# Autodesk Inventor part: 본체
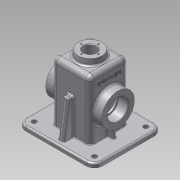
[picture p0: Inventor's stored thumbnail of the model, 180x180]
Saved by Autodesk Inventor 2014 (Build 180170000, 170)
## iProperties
Created: 2016-08
Part Number: 본체
Material: 알루미늄 6061
Document SubType Name: Modeling
Designer: user
Density: 2.71 g/cm^3
Appearance: 알루미늄 - 평지
Mass: 800.3 g
Surface Area: 911.822 cm^2
Volume: 295.314 cm^3
Author: user
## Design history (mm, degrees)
sketch "스케치1"
  geometry: L1 (-60, 52.5)-(60, 52.5); L2 (60, 52.5)-(60, -52.5); L3 (60, -52.5)-(-60, -52.5); L4 (-60, -52.5)-(-60, 52.5); 3 further points
  constraints: 8 end point, 2 midpoint, 2 parallel, 1 horizontal, 1 horizontal alignment, 1 perpendicular, 1 vertical alignment
  dimensions: "d0" = 120 distance of L1.start L1.end; "d1" = 105 distance of L1.end L2.end
extrude "돌출1" new body sketch "스케치1" distance "d2" = 3; taper "d3" = 0 deg
sketch "스케치2"
  geometry: L1 (-65, 57.5)-(65, 57.5); L2 (65, 57.5)-(65, -57.5); L3 (65, -57.5)-(-65, -57.5); L4 (-65, -57.5)-(-65, 57.5); 3 further points
  constraints: 8 end point, 2 midpoint, 2 parallel, 1 horizontal, 1 horizontal alignment, 1 perpendicular, 1 vertical alignment
  dimensions: "d4" = 115 distance of L1.end L2.end; "d5" = 130 distance of L1.start L1.end
extrude "돌출2" join sketch "스케치2" distance "d6" = 7; taper "d7" = 0 deg
fillet "모깎기1" dims "d8" = 14
fillet "모깎기2" dims "d9" = 3
sketch "스케치3"
  geometry: L1 (32.5, 110)-(-32.5, 110); L2 (-32.5, 110)-(-32.5, 0); L3 (-32.5, 0)-(32.5, 0); L4 (32.5, 0)-(32.5, 110); 2 further points
  constraints: 8 end point, 2 parallel, 1 coincident, 1 horizontal, 1 midpoint, 1 perpendicular
  dimensions: "d10" = 65 distance of L1.start L1.end; "d11" = 110 distance of L1.end L2.end
extrude "돌출3" join sketch "스케치3" stored distance "d12" = 65; taper "d13" = 0 deg
fillet "모깎기3" dims "d14" = 8
fillet "모깎기4" dims "d15" = 8
sketch "스케치4"
  geometry: L1 (27.5, 105)-(-27.5, 105); L2 (-27.5, 105)-(-27.5, 0); L3 (-27.5, 0)-(27.5, 0); L4 (27.5, 0)-(27.5, 105); 2 further points
  constraints: 8 end point, 2 parallel, 1 coincident, 1 horizontal, 1 midpoint, 1 perpendicular
  dimensions: "d18" = 105 distance of L1.end L2.end; "d19" = 55 distance of L1.start L1.end
extrude "돌출4" cut sketch "스케치4" stored distance "d20" = 55; taper "d21" = 0 deg
fillet "모깎기6" dims "d22" = 3
fillet "모깎기7" dims "d23" = 3
node "작업 평면1"
sketch "스케치5"
  geometry: C1 r 20 at (0, 0); 1 further point
  constraints: 1 centre point, 1 coincident
  dimensions: "d25" = 40 diameter of C1
extrude "돌출5" join sketch "스케치5" stored distance "d26" = 55; taper "d27" = 7 deg
fillet "모깎기8" dims "d28" = 3
hole "구멍1" diameter "d31" = 21; stored, may be unused: countersink angle "d35" = 90 deg, drill point angle "d37" = 0 deg; dims "d29" = 10, "d30" = 10, "d32" = 6, "d33" = 4, "d34" = 2, "d36" = 8
chamfer "모따기1" distance "d38" = 1; stored, may be unused: second distance "d39" = 2, angle "d40" = 45 deg
node "작업 평면2"
sketch "스케치6"
  geometry: C1 r 27.5 at (0, 55); 1 further point
  constraints: 1 centre point, 1 vertical alignment
  dimensions: "d42" = 55 diameter of C1; "d43" = 55 distance of point (0, 0) C1.centre
extrude "돌출6" join sketch "스케치6" stored distance "d44" = 95; taper "d45" = 0 deg
fillet "모깎기9" dims "d46" = 3
hole "구멍2" diameter "d49" = 30; stored, may be unused: countersink angle "d53" = 90 deg, drill point angle "d55" = 0 deg; dims "d47" = 10, "d48" = 10, "d50" = 6, "d51" = 35, "d52" = 17, "d54" = 8
hole "구멍3" diameter "d58" = 30; stored, may be unused: countersink angle "d62" = 90 deg, drill point angle "d64" = 0 deg; dims "d56" = 10, "d57" = 10, "d59" = 6, "d60" = 35, "d61" = 17, "d63" = 8
chamfer "모따기2" distance "d65" = 1; stored, may be unused: second distance "d66" = 2, angle "d67" = 45 deg
fillet "모깎기10" dims "d68" = 0.3
sketch "스케치7"
  geometry: L1 (-43.5, 10)-(43.5, 10) reference; L2 (-32.5, 10)-(-32.5, 102) reference; L3 (-54.5, 10)-(-43.5, 10) reference; L4 (-57.5, 3)-(-57.5, 7) reference; L5 (-52.5, 0)-(52.5, 0) reference; L6 (-49.5, 10)-(-41.068, 70); L7 (-41.068, 70)-(-32.5, 70); 2 further points
  constraints: 4 end point, 2 point on line, 1 perpendicular
  dimensions: "d71" = 8 distance from line of L4 L6.start; "d72" = 8 deg angle of L4 L6; "d73" = 70 distance between parallel lines of L5 L7
feature "리브1" sketch "스케치7" dims "d74" = 1, "d75" = 10, "d76" = 0, "d77" = 0, "d78" = 1, "d79" = 1
fillet "모깎기11" dims "d80" = 3
fillet "모깎기12" dims "d81" = 3
fillet "모깎기13" dims "d82" = 3
fillet "모깎기15" dims "d84" = 3
hole "구멍4" diameter "d88" = 8; stored, may be unused: countersink angle "d92" = 90 deg, drill point angle "d94" = 0 deg; dims "d86" = 10, "d87" = 10, "d89" = 6, "d90" = 35, "d91" = 17, "d93" = 8
hole "구멍5" diameter "d97" = 8; stored, may be unused: countersink angle "d101" = 90 deg, drill point angle "d103" = 0 deg; dims "d95" = 10, "d96" = 10, "d98" = 6, "d99" = 35, "d100" = 17, "d102" = 8
hole "구멍6" diameter "d106" = 8; stored, may be unused: countersink angle "d110" = 90 deg, drill point angle "d112" = 0 deg; dims "d104" = 10, "d105" = 10, "d107" = 6, "d108" = 35, "d109" = 17, "d111" = 8
hole "구멍7" diameter "d115" = 8; stored, may be unused: countersink angle "d119" = 90 deg, drill point angle "d121" = 0 deg; dims "d113" = 10, "d114" = 10, "d116" = 6, "d117" = 35, "d118" = 17, "d120" = 8
sketch "스케치8"
  geometry: 2 further points
  constraints: 1 vertical alignment
  dimensions: "d122" = 14.5 distance of point (0, 0) point (0, 14.5)
hole "구멍8" sketch "스케치8" at (0, 14.5) diameter "d123" = 2.459; stored, may be unused: countersink angle "d127" = 90 deg, drill point angle "d129" = 118 deg; dims "d124" = 7, "d125" = 35, "d126" = 17, "d128" = 9
sketch "스케치9"
  geometry: C1 r 27.5 at (0, 0) reference; 2 further points
  constraints: 1 horizontal alignment
  dimensions: "d133" = 21 distance of C1.centre point (21, 0)
hole "구멍9" sketch "스케치9" at (21, 0) diameter "d134" = 3.242; stored, may be unused: countersink angle "d138" = 90 deg, drill point angle "d140" = 118 deg; dims "d135" = 8, "d136" = 35, "d137" = 17, "d139" = 10
sketch "스케치10"
  geometry: L1 (-18, 4.5)-(-18, 44.5) reference; L2 (0, -8)-(92, -8) reference; 3 further points
  constraints: 1 other
  dimensions: "d144" = 26 distance from line of L1 point (8, 24.5); "d145" = 32.5 distance from line of L2 point (8, 24.5)
feature "엠보싱1" sketch "스케치10" dims "d146" = 0.5, "d147" = 0
sketch "스케치11"
  geometry: L1 (51, 10)-(-51, 10) reference; L2 (35.5, 27.5)-(47.5, 27.5) reference; L3 (42.5, 10)-(42.5, 27.5); L4 (27.5, 102)-(27.5, 0) reference; 1 further point
  constraints: 2 end point, 2 point on line, 1 perpendicular
  dimensions: "d148" = 15 distance between parallel lines of L3 L4
feature "리브2" sketch "스케치11" dims "d149" = 1, "d150" = 6, "d151" = 0, "d152" = 0, "d153" = 1, "d154" = 1
fillet "모깎기17" dims "d155" = 3
fillet "모깎기18" dims "d156" = 3
fillet "모깎기19" dims "d157" = 1
fillet "모깎기20" dims "d158" = 9
node "솔리드1"
mirror "대칭1"
mirror "대칭2"
pattern_circular "원형 패턴1" dims angle "d131" = 360 deg
pattern_circular "원형 패턴2" dims angle "d142" = 360 deg
mirror "대칭3"
mirror "대칭4"
other parameters: "d41" = 47.5
